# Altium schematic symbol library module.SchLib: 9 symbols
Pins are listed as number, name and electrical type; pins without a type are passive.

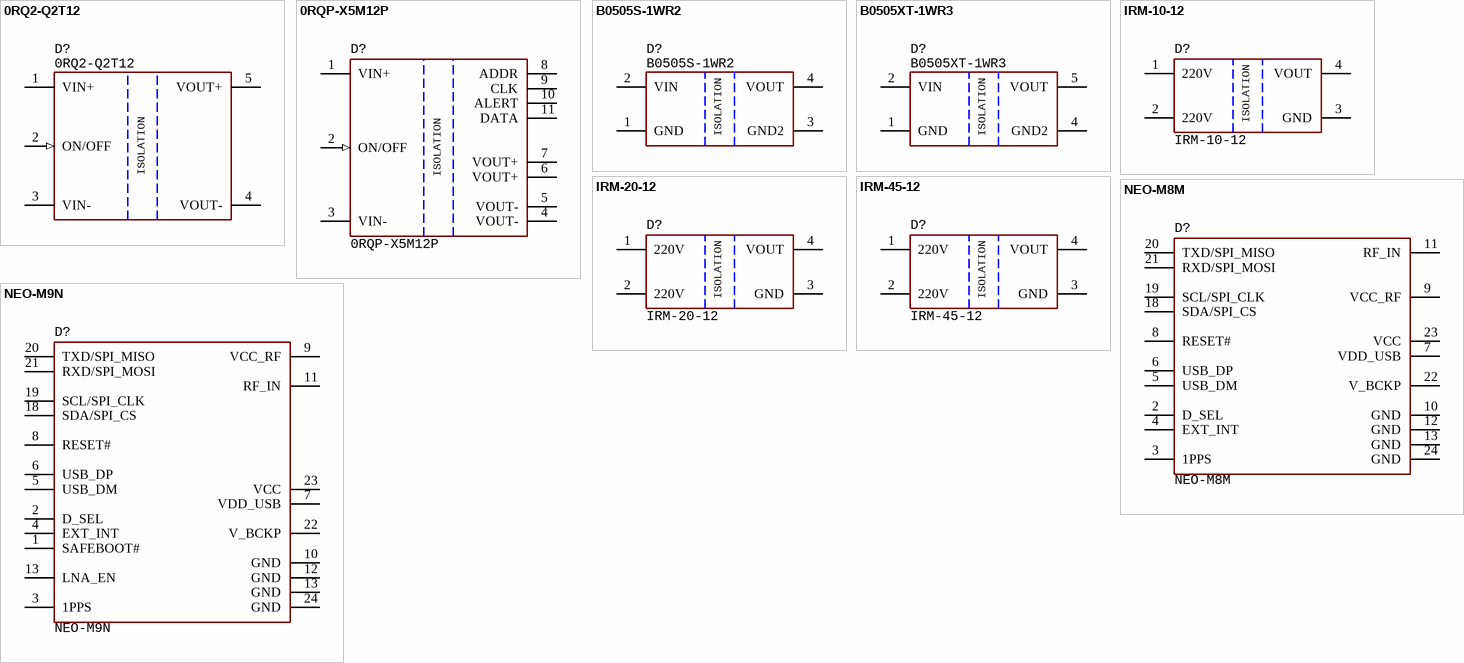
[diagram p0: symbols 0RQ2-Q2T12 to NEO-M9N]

## 0RQ2-Q2T12
designator D?
Brick 1/4, 420W, input 36-75VDC, outpit 12V, 35A, 1500Vrms, -40...+85°C; Manufacture: BelFuse
footprint MOD: 0RQ2-Q2T12
pins: 1 VIN+, 2 ON/OFF (in), 3 VIN-, 4 VOUT-, 5 VOUT+

## 0RQP-X5M12P
designator D?
Brick 1/4, 1500W, input 48...60V, output 12V, -20...+85°C; Manufacturer: BelFuse; Manufacturer: Bel; Manufacturer Part Number: 0RQP-X5M12PG
footprint MOD: 0RQP-X5M12P
pins: 1 VIN+, 2 ON/OFF (in), 3 VIN-, 4 VOUT-, 5 VOUT-, 6 VOUT+, 7 VOUT+, 8 ADDR, 9 CLK, 10 ALERT, 11 DATA

## B0505S-1WR2
designator D?
DC/DC isolator, 1W, input 4.5...5.5V, 200 mA, 1500 Vrms, SIP-4, -40...+105°C; Manufacture: Mornsun
footprint MOD: SIP-4 (B0505S-1W)
pins: 1 GND (power), 2 VIN (power), 3 GND2 (power), 4 VOUT (power)

## B0505XT-1WR3
designator D?
DC/DC isolator, 1W, input 4.5...5.5V, 200 mA, 1500 Vrms, SMD-8, -40...+105°C; Manufacture: Mornsun
footprint MOD: B0505XT-1WR3
pins: 1 GND (power), 2 VIN (power), 4 GND2 (power), 5 VOUT (power)

## IRM-10-12
designator D?
AC/DC Module, 12V, 10W, 0.85A, Isolator, 85...265VAC, -30...+70°C; Manufacturer: Mean Well
footprint MOD: IRM-10-12
pins: 1 220V (power), 2 220V (power), 3 GND (power), 4 VOUT (power)

## IRM-20-12
designator D?
AC/DC Module, 12V, 20W, 1.8A, Isolator, 85...265VAC, -30...+70°C; Manufacturer: Mean Well
footprint MOD: IRM-20-12
pins: 1 220V (power), 2 220V (power), 3 GND (power), 4 VOUT (power)

## IRM-45-12
designator D?
AC/DC Module, 12V, 45W, 3.8A, Isolator, 85...265VAC, -30...+70°C; Manufacturer: Mean Well
footprint MOD: IRM-45-12
pins: 1 220V (power), 2 220V (power), 3 GND (power), 4 VOUT (power)

## NEO-M8M
designator D?
GPS Module, -164 dBm, 1.65...3.6V, -40...+85°C; Manufacturer: uBlox
footprint MOD: NEO-8M
pins: 2 D_SEL, 3 1PPS, 4 EXT_INT, 5 USB_DM, 6 USB_DP, 7 VDD_USB, 8 RESET#, 9 VCC_RF, 10 GND, 11 RF_IN, 12 GND, 13 GND, 18 SDA/SPI_CS, 19 SCL/SPI_CLK, 20 TXD/SPI_MISO, 21 RXD/SPI_MOSI, 22 V_BCKP, 23 VCC, 24 GND

## NEO-M9N
designator D?
GPS Module, -167 dBm, 2.7...3.6V, -40...+85°C; Manufacturer: uBlox
footprint MOD: NEO-8M
pins: 1 SAFEBOOT#, 2 D_SEL, 3 1PPS, 4 EXT_INT, 5 USB_DM, 6 USB_DP, 7 VDD_USB, 8 RESET#, 9 VCC_RF, 10 GND, 11 RF_IN, 12 GND, 13 GND, 13 LNA_EN, 18 SDA/SPI_CS, 19 SCL/SPI_CLK, 20 TXD/SPI_MISO, 21 RXD/SPI_MOSI, 22 V_BCKP, 23 VCC, 24 GND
